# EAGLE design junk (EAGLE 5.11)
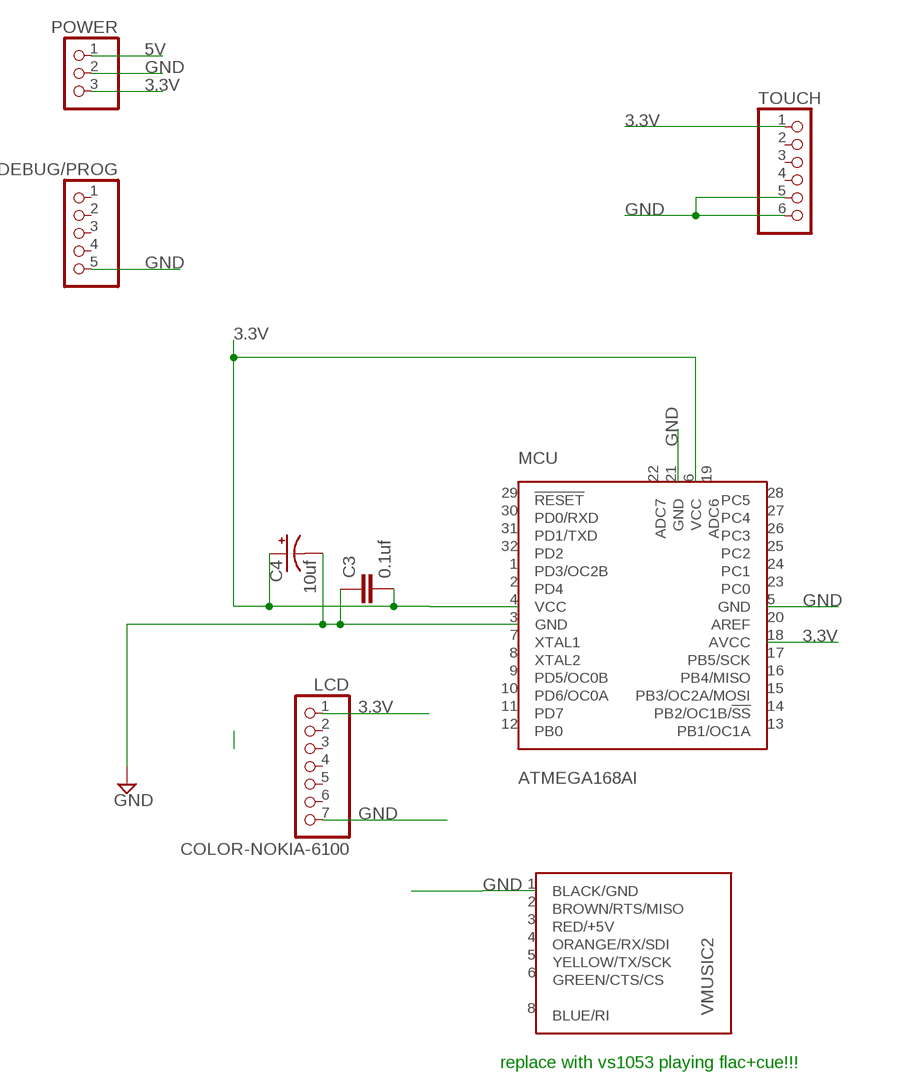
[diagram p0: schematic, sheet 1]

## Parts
C3  0.1uf  C-EUC0805  [C0805]
C4  10uf  CPOL-USE2-4  [E2-4]
DEBUG/PROG  PINHD-1X5  [1X05]
LCD  COLOR-NOKIA-6100  PINHD-1X7  [1X07]
MCU  ATMEGA168AI  [TQFP32-08]
POWER  PINHD-1X3  [1X03]
TOUCH  PINHD-1X6  [1X06]
VMUSIC2  VMUSIC2  [VMUSIC2]

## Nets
3.3V: C3.2 C4.+ LCD.1 MCU.4(VCC) MCU.6(VCC) MCU.18(AVCC) POWER.3 TOUCH.1
5V: POWER.1
GND: C3.1 C4.- DEBUG/PROG.5 LCD.7 MCU.3(GND) MCU.5(GND) MCU.21(GND) POWER.2 TOUCH.5 TOUCH.6 VMUSIC2.1(BLACK/GND)
Unconnected: DEBUG/PROG.1 DEBUG/PROG.2 DEBUG/PROG.3 DEBUG/PROG.4 LCD.2 LCD.3 LCD.4 LCD.5 LCD.6 MCU.1(PD3/OC2B) MCU.2(PD4) MCU.7(XTAL1) MCU.8(XTAL2) MCU.9(PD5/OC0B) MCU.10(PD6/OC0A) MCU.11(PD7) MCU.12(PB0) MCU.13(PB1/OC1A) MCU.14(PB2/OC1B/!SS) MCU.15(PB3/OC2A/MOSI) MCU.16(PB4/MISO) MCU.17(PB5/SCK) MCU.19(ADC6) MCU.20(AREF) MCU.22(ADC7) MCU.23(PC0) MCU.24(PC1) MCU.25(PC2) MCU.26(PC3) MCU.27(PC4) MCU.28(PC5) MCU.29(!RESET) MCU.30(PD0/RXD) MCU.31(PD1/TXD) MCU.32(PD2) TOUCH.2 TOUCH.3 TOUCH.4 VMUSIC2.2(BROWN/RTS/MISO) VMUSIC2.3(RED/+5V) VMUSIC2.4(ORANGE/RX/SDI) VMUSIC2.5(YELLOW/TX/SCK) VMUSIC2.6(GREEN/CTS/CS) VMUSIC2.8(BLUE/RI)

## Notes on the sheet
- replace with vs1053 playing flac+cue!!!

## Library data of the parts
C3 = rcl:C-EU: CAPACITOR, European symbol
C4 = rcl:CPOL-US: POLARIZED CAPACITOR, American symbol
DEBUG/PROG = pinhead:PINHD-1X5: PIN HEADER
LCD = pinhead:PINHD-1X7: PIN HEADER
MCU = trl:ATMEGA168
POWER = pinhead:PINHD-1X3: PIN HEADER
TOUCH = pinhead:PINHD-1X6: PIN HEADER
VMUSIC2 = trl:VMUSIC2

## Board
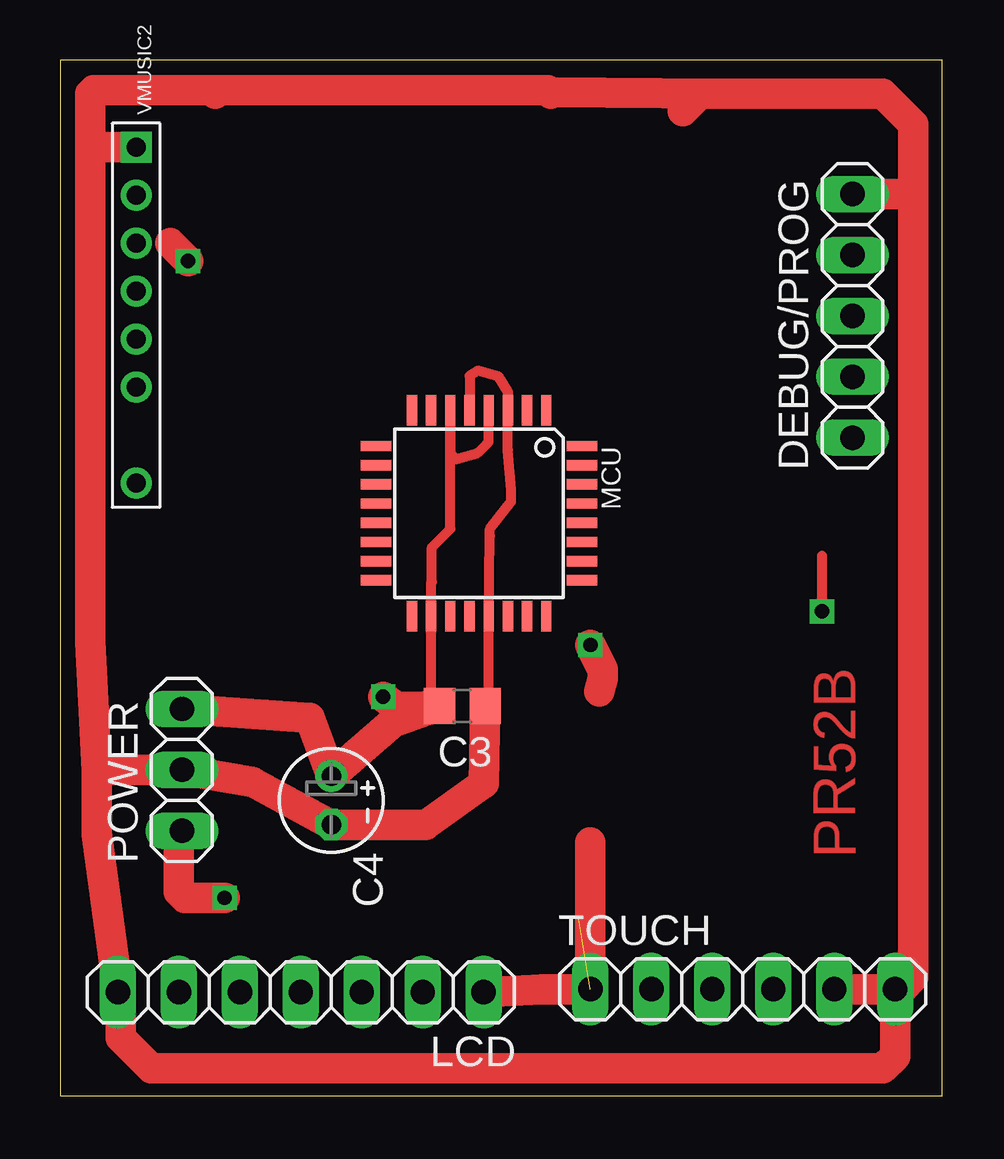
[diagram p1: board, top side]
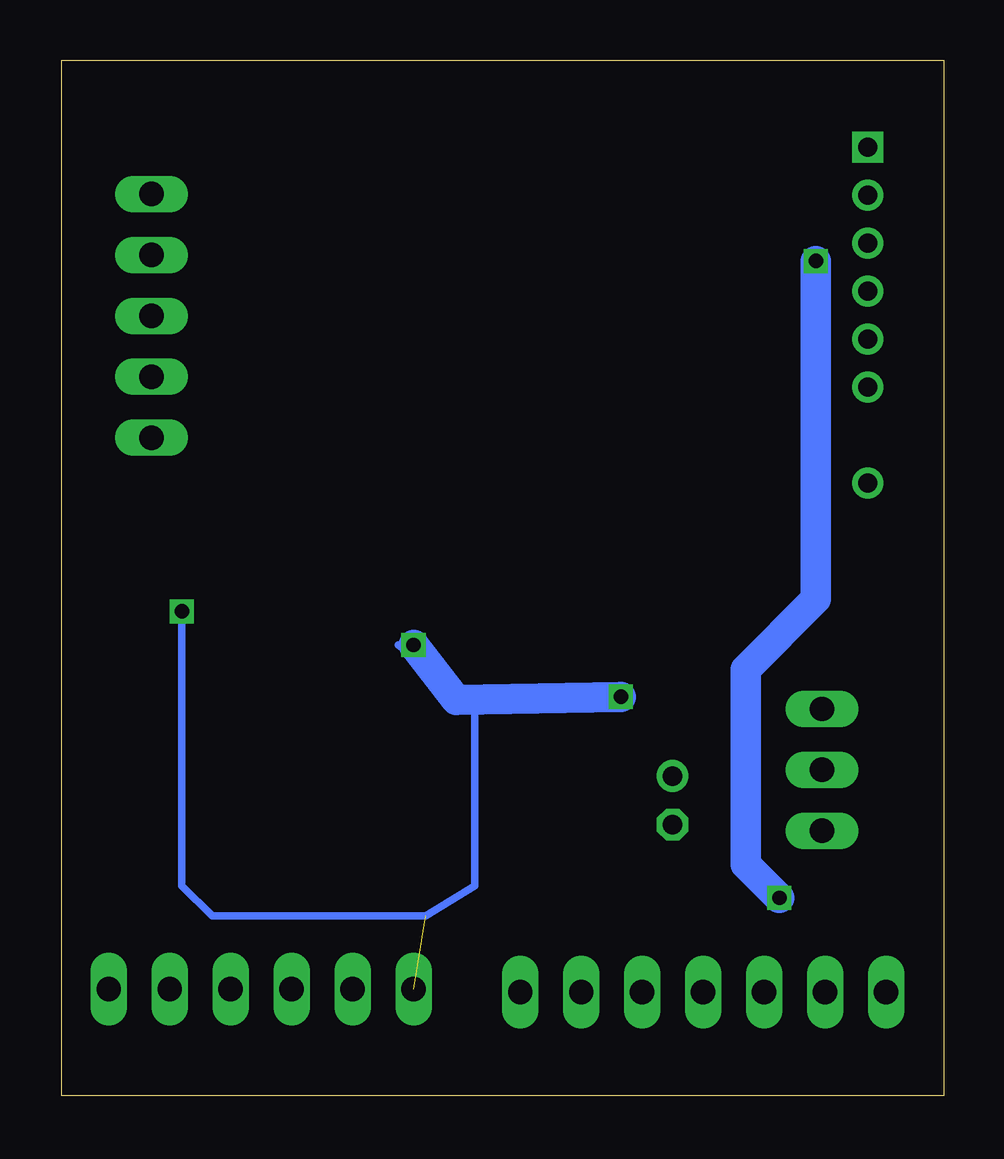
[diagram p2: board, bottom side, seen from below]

Size 36.75 x 43.17 mm. Coordinates in mm from the lower left corner, seen from the top.
Outline: 0,0 36.75,0 36.75,43.17 0,43.17 0,0
Copper layers (1*16): Top 0.035mm / dielectric 1.5mm / Bottom 0.035mm
Design rules "default": minimum track width 10mil, minimum drill 24mil, track to track 8mil, track to pad 8mil, pad to pad 8mil, via to via 8mil, smd to smd 8mil, copper to edge 40mil, drill to drill 8mil, minimum pad ring 10mil, minimum via ring 8mil, stop-mask expansion 4mil, vias tented up to drill 0mil, thermal gap 10mil

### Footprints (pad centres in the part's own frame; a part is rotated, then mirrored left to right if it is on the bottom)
C0805 = smd 1.3 x 1.5: 1 -0.95,0; 2 0.95,0
E2-4 = drill 0.813 pad 1.27 round: + -1.016,0 | drill 0.813 pad 1.27 octagon: - 1.016,0
1X05 = drill 1.016 long: 1 -5.08,0; 2 -2.54,0; 3 0,0; 4 2.54,0; 5 5.08,0
1X07 = drill 1.016 long: 1 -7.62,0; 2 -5.08,0; 3 -2.54,0; 4 0,0; 5 2.54,0; 6 5.08,0; 7 7.62,0
TQFP32-08 = smd 1.27 x 0.432: 1 -3.563,2.61; 2 -3.563,1.81; 3 -3.563,1.01; 4 -3.563,0.21; 5 -3.563,-0.59; 6 -3.563,-1.39; 7 -3.563,-2.19; 8 -3.563,-2.99; 17 5.023,-2.99; 18 5.023,-2.19; 19 5.023,-1.39; 20 5.023,-0.59; 21 5.023,0.21; 22 5.023,1.01; 23 5.023,1.81; 24 5.023,2.61 | smd 0.432 x 1.27: 9 -2.07,-4.483; 10 -1.27,-4.483; 11 -0.47,-4.483; 12 0.33,-4.483; 13 1.13,-4.483; 14 1.93,-4.483; 15 2.73,-4.483; 16 3.53,-4.483; 25 3.53,4.103; 26 2.73,4.103; 27 1.93,4.103; 28 1.13,4.103; 29 0.33,4.103; 30 -0.47,4.103; 31 -1.27,4.103; 32 -2.07,4.103
1X03 = drill 1.016 long: 1 -2.54,0; 2 0,0; 3 2.54,0
1X06 = drill 1.016 long: 1 -6.35,0; 2 -3.81,0; 3 -1.27,0; 4 1.27,0; 5 3.81,0; 6 6.35,0
VMUSIC2 = drill 0.8 square: 1 5,0 | drill 0.8 round: 2 3,0; 3 1,0; 4 -1,0; 5 -3,0; 6 -5,0; 8 -9,0

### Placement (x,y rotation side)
C3  16.76,16.26 180 top
C4  11.3,12.32 270 top
DEBUG/PROG  33.02,32.51 90 top
LCD  10.03,4.32 180 top
MCU  17.65,25.02 270 top
POWER  5.08,13.59 90 top
TOUCH  28.45,4.45 0 top
VMUSIC2  3.17,34.54 90 top

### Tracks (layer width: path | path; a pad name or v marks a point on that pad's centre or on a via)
3.3V  (via drill 0.6)  (1 unrouted)
  Top 0.406: 15.35,16.09 15.46,16.21 MCU.18 15.46,21.39 15.49,21.42 15.49,22.86 16.26,23.63 MCU.6 16.26,26.79 16.51,26.54 17.4,26.8 | 17.4,26.8 17.78,27.18 | v31.75,20.19 31.75,22.5 | MCU.4 17.86,27.26 17.4,26.8
  Top 1.27: POWER.3 10.41,15.75 C4.+ 13.84,15.55 C3.2 15.29,16.26 15.24,16.21 | LCD.1 20.07,4.45 TOUCH.1 22.1,10.57 | 15.24,16.21 14.02,16.21 v13.46,16.64 | 15.24,16.21 15.46,16.21 15.35,16.09 | v22.1,18.8 22.61,17.78 22.61,17.4 22.48,16.87
  Bottom 0.305: v22.1,18.8 22.73,18.8 19.56,16.38 19.56,8.76 21.59,7.49 30.48,7.49 31.75,8.76 v31.75,20.19
  Bottom 1.27: v13.46,16.64 20.32,16.51 v22.1,18.8
5V  (via drill 0.6)
  Top 1.27: POWER.1 4.95,10.92 4.95,8.51 5.21,8.25 v6.86,8.25 | v5.33,34.8 4.59,35.54
  Bottom 1.27: v5.33,34.8 5.33,20.7 8.26,17.78 8.26,9.65 v6.86,8.25
GND
  Top 0.406: MCU.5 17.06,30.02 17.4,30.23 18.29,29.97 18.67,29.34 18.67,28.7 MCU.3 18.66,26.93 18.8,25.27 18.8,24.77 17.91,23.62 17.91,23.34 MCU.21 17.86,16.41 C3.1
  Top 1.27: 6.35,41.91 1.4,41.91 1.27,41.78 1.27,39.24 | 1.27,39.24 1.27,25.27 1.27,22.73 | 1.27,22.73 1.27,21.84 | C3.1 17.65,13.01 15.24,11.3 13.97,11.3 C4.- 8,13.08 POWER.2 1.91,13.59 1.52,13.21 1.52,10.92 | 6.35,41.91 6.48,41.78 | 20.38,41.85 27.43,41.78 | 25.94,41.05 26.67,41.78 27.43,41.78 | 2.54,3.56 2.54,4.19 LCD.7 | 2.54,3.56 2.54,2.41 3.81,1.14 34.29,1.14 34.8,1.65 TOUCH.6 | 27.43,41.78 34.29,41.78 35.56,40.51 35.56,37.97 | 35.56,37.97 35.56,6.22 35.56,5.21 | 6.35,41.91 20.32,41.91 20.38,41.85 | 20.38,41.85 20.45,41.78 | 2.54,3.56 1.52,10.92 | 1.27,22.73 1.27,18.92 1.52,13.59 1.52,10.92 | DEBUG/PROG.5 35.18,37.59 35.56,37.97 | VMUSIC2.1 1.57,39.54 1.27,39.24 | TOUCH.6 35.05,4.45 35.56,4.95 | TOUCH.6 TOUCH.5

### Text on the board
Top: PR52B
